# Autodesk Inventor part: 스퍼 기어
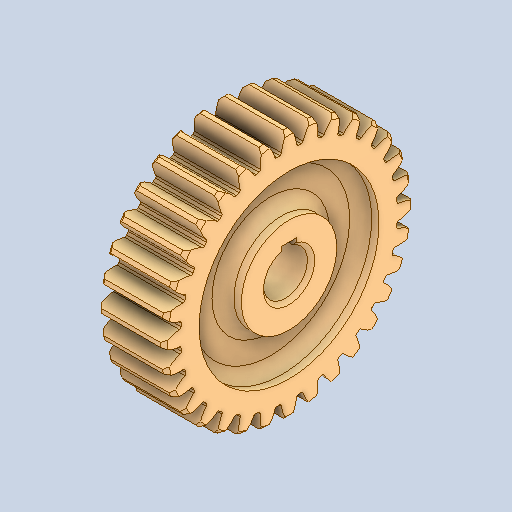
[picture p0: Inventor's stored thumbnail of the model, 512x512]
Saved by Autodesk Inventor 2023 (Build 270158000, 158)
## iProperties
Created: 2026-06
Part Number: 스퍼 기어
Material: 강철, 합금
Document SubType Name: Modeling
Designer: 4강의실
Density: 7.73 g/cm^3
Appearance: 기본값
Author: jhkim
Sending System: Autodesk Inventor 2027
Preprocessor: ST-DEVELOPER v20.1
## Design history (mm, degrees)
feature "솔리드1"
node "솔리드2"
